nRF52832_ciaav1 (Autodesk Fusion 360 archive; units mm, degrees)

design "nRF52832_ciaa"
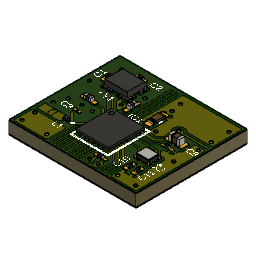
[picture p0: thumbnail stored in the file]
sketch "Outline" plane through (0, 0, 0) normal (0, 0, 1) x axis (1, 0, 0)
  line L1 (11.44, 0) -> (0, 0)
  line L2 (11.44, 10) -> (11.44, 0)
  line L3 (0, 10) -> (11.44, 10)
  line L4 (0, 0) -> (0, 10)
canvas "Canvas1" bodies "Board"
canvas "Canvas2" bodies "Board"
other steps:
base_feature "Base Feature1"
base_feature "Base Feature1"
base_feature "Base Feature1"
pcbextrude "PCBExtrude1"
pcbextrude "PCBExtrude1"
pcbextrude "PCBExtrude1"
pcbextrude "PCBExtrude1"
base_feature "Base Feature1"
base_feature "Base Feature1"
base_feature "Base Feature1"
base_feature "Base Feature1"
base_feature "Base Feature1"
base_feature "Base Feature1"
base_feature "Base Feature1"
base_feature "Base Feature1"
base_feature "Base Feature1"
base_feature "Base Feature1"
base_feature "Base Feature1"
base_feature "Base Feature1"
base_feature "Base Feature1"
base_feature "Base Feature1"
base_feature "Base Feature1"
base_feature "Base Feature1"
base_feature "Base Feature1"
base_feature "Base Feature1"
base_feature "Base Feature1"
base_feature "Base Feature1"
base_feature "Base Feature1"
base_feature "Base Feature1"
base_feature "Base Feature1"
base_feature "Base Feature1"
base_feature "Base Feature1"
base_feature "Base Feature1"
base_feature "Base Feature1"
base_feature "Base Feature1"
base_feature "Base Feature1"
base_feature "Base Feature1"
base_feature "Base Feature1"
base_feature "Base Feature1"
base_feature "Base Feature1"
base_feature "Base Feature1"
base_feature "Base Feature1"
base_feature "Base Feature1"
base_feature "Base Feature1"
base_feature "Base Feature1"
base_feature "Base Feature1"
base_feature "Base Feature1"
base_feature "Base Feature1"
base_feature "Base Feature1"
base_feature "Base Feature1"
base_feature "Base Feature1"
base_feature "Base Feature1"
base_feature "Base Feature1"
base_feature "Base Feature1"
base_feature "Base Feature1"
base_feature "Base Feature1"
base_feature "Base Feature1"
base_feature "Base Feature1"
base_feature "Base Feature1"
base_feature "Base Feature1"
base_feature "Base Feature1"
base_feature "Base Feature1"
base_feature "Base Feature1"
base_feature "Base Feature1"
base_feature "Base Feature1"
base_feature "Base Feature1"
base_feature "Base Feature1"
base_feature "Base Feature1"
base_feature "Base Feature1"
base_feature "Base Feature1"
extrude "Extrude1" sketch "Outline" blind 1.037 bodies "Board"
pcbextrude "PCBExtrude1"
pcbextrude "PCBExtrude3" bodies "CopperHoles"
create_component "CreateComponent1"
create_component "CreateComponent2"
create_component "CreateComponent3"
create_component "CreateComponent4"
create_component "CreateComponent5"
create_component "CreateComponent6"
create_component "CreateComponent1"
create_component "CreateComponent2"
create_component "CreateComponent1"
create_component "CreateComponent2"
create_component "CreateComponent3"
create_component "CreateComponent1"
create_component "CreateComponent2"
create_component "CreateComponent3"
create_component "CreateComponent4"
create_component "CreateComponent5"
create_component "CreateComponent1"
create_component "CreateComponent2"
create_component "CreateComponent3"
create_component "CreateComponent4"
create_component "CreateComponent5"
create_component "CreateComponent6"
create_component "CreateComponent7"
create_component "CreateComponent8"
create_component "CreateComponent9"
create_component "CreateComponent10"
create_component "CreateComponent11"
create_component "CreateComponent12"
create_component "CreateComponent13"
create_component "CreateComponent14"
create_component "CreateComponent15"
create_component "CreateComponent16"
create_component "CreateComponent17"
create_component "CreateComponent18"
create_component "CreateComponent19"
create_component "CreateComponent20"
create_component "CreateComponent21"
create_component "CreateComponent22"
create_component "CreateComponent23"
create_component "CreateComponent24"
create_component "CreateComponent25"
create_component "CreateComponent26"
create_component "CreateComponent27"
create_component "CreateComponent28"
create_component "CreateComponent29"
create_component "CreateComponent30"
create_component "CreateComponent31"
create_component "CreateComponent32"
create_component "CreateComponent33"
create_component "CreateComponent34"
create_component "CreateComponent35"
create_component "CreateComponent36"
create_component "CreateComponent37"
create_component "CreateComponent38"
create_component "CreateComponent39"
create_component "CreateComponent40"
create_component "CreateComponent41"
create_component "CreateComponent42"
create_component "CreateComponent43"
create_component "CreateComponent44"
create_component "CreateComponent45"
create_component "CreateComponent46"
create_component "CreateComponent47"
create_component "CreateComponent48"
create_component "CreateComponent49"
create_component "CreateComponent50"
create_component "CreateComponent51"
create_component "CreateComponent7"
create_component "CreateComponent8"
create_component "CreateComponent9"
create_component "CreateComponent10"
as_built_joint "As-built1"
create_component "CreateComponent7"
create_component "CreateComponent8"
create_component "CreateComponent9"
create_component "CreateComponent10"
create_component "CreateComponent11"
named bodies: "Board", "CopperHoles"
